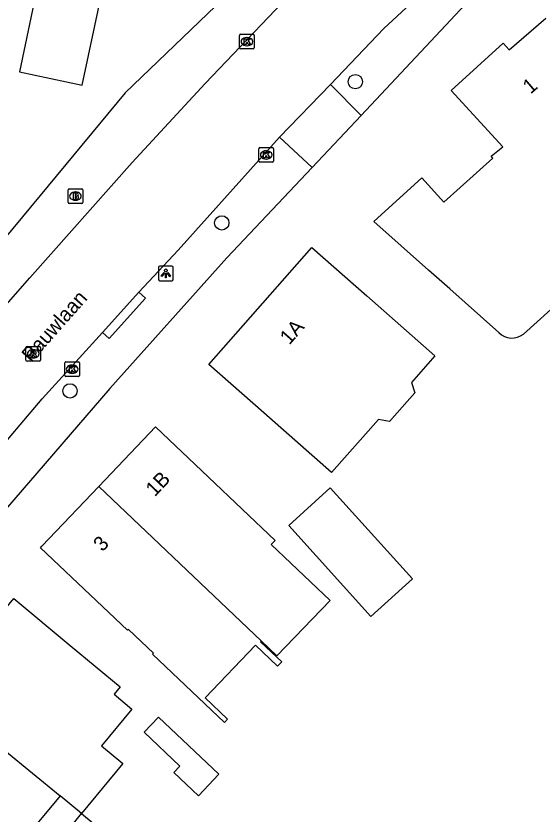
# Model space of a CAD drawing. Extents: x 161772 to 163123, y 383092 to 383917.
# Drawn here: x 162519.5 to 162555.4, y 383557.9 to 383612.4 of the extents above; entities that cross this region are included whole.
import ezdxf

# ---------------------------------------------------------------- set-up
doc = ezdxf.new("R2010")
doc.units = 0
for name, color, linetype in [('IMGEO_Boom', 7, 'Continuous'), ('IMGEO_Brandkraan', 7, 'Continuous'), ('IMGEO_Kolk', 7, 'Continuous'), ('IMGEO_Lichtpunt', 7, 'Continuous'), ('IMGEO_Openbare_ruimte_label', 7, 'Continuous'), ('IMGEO_Pand', 7, 'Continuous'), ('IMGEO_Pand_nummerreeks', 7, 'Continuous'), ('IMGEO_Rijbaan_lokaal_open', 7, 'Continuous'), ('IMGEO_Rioolput', 7, 'Continuous'), ('IMGEO_Voetpad_open', 7, 'Continuous')]:
    doc.layers.add(name, color=color, linetype=linetype)

msp = doc.modelspace()

# ---------------------------------------------------------------- linework, layer by layer
at = {"layer": 'IMGEO_Boom'}
for centre in [(162542.653, 383607.887), (162533.543, 383598.255), (162523.191, 383586.794)]:
    msp.add_circle(centre, 0.489, dxfattribs=at)
at = {"layer": 'IMGEO_Brandkraan'}
for p, q in [((162523.058, 383599.658), (162523.058, 383600.51)), ((162523.133, 383600.584), (162523.985, 383600.584)), ((162523.546, 383600.364), (162523.571, 383600.364)), ((162524.059, 383600.51), (162524.059, 383599.658)), ((162523.569, 383599.804), (162523.544, 383599.804)), ((162523.985, 383599.584), (162523.133, 383599.584))]:
    msp.add_line(p, q, dxfattribs=at)
for points in [[(162523.058, 383599.658), (162523.058, 383600.51)], [(162523.133, 383600.584), (162523.985, 383600.584)], [(162523.406, 383600.284), (162523.406, 383599.884), (162523.619, 383599.884)], [(162523.637, 383600.284), (162523.406, 383600.284)], [(162524.059, 383600.51), (162524.059, 383599.658)], [(162523.585, 383600.203), (162523.531, 383600.203), (162523.531, 383600.127)], [(162523.531, 383600.127), (162523.584, 383600.127)], [(162523.593, 383600.051), (162523.531, 383600.051), (162523.531, 383599.97)], [(162523.531, 383599.97), (162523.593, 383599.97)], [(162523.985, 383599.584), (162523.133, 383599.584)]]:
    msp.add_lwpolyline(points, dxfattribs=at)
for centre, radius, start, end in [((162523.135, 383600.508), 0.0765, 91.552, 178.448), ((162523.135, 383600.508), 0.0765, 91.552, 178.448), ((162523.641, 383600.139), 0.145, 59.4692, 91.5367), ((162523.666, 383600.186), 0.0922, 285.5137, 58.1501), ((162523.983, 383600.508), 0.0765, 1.552, 88.448), ((162523.983, 383600.508), 0.0765, 1.552, 88.448), ((162523.586, 383600.165), 0.0379, 267.8285, 90.9355), ((162523.594, 383600.01), 0.0404, 269.8759, 90.5077), ((162523.625, 383600.135), 0.251, 268.6676, 293.5347), ((162523.671, 383599.994), 0.105, 301.3115, 78.989), ((162523.135, 383599.66), 0.0765, 181.552, 268.448), ((162523.135, 383599.66), 0.0765, 181.552, 268.448), ((162523.983, 383599.66), 0.0765, 271.552, 358.448), ((162523.983, 383599.66), 0.0765, 271.552, 358.448)]:
    msp.add_arc(centre, radius, start, end, dxfattribs=at)
for centre, major_axis, ratio, start_param, end_param in [((162523.545, 383600.084), (-0.387, 0.002), 0.722429, 4.712389, 7.853982), ((162523.57, 383600.084), (-0.39, 0.002), 0.717154, 1.570796, 4.712389)]:
    msp.add_ellipse(centre, major_axis=major_axis, ratio=ratio, start_param=start_param, end_param=end_param, dxfattribs=at)
at = {"layer": 'IMGEO_Kolk'}
for p, q in [((162534.757, 383610.196), (162534.757, 383611.048)), ((162534.832, 383611.122), (162535.684, 383611.122)), ((162535.245, 383610.902), (162535.27, 383610.902)), ((162535.758, 383611.048), (162535.758, 383610.196)), ((162535.684, 383610.122), (162534.832, 383610.122)), ((162535.268, 383610.342), (162535.243, 383610.342)), ((162536.073, 383602.464), (162536.073, 383603.316)), ((162536.148, 383603.39), (162537, 383603.39)), ((162536.561, 383603.17), (162536.586, 383603.17)), ((162537.074, 383603.316), (162537.074, 383602.464)), ((162536.584, 383602.61), (162536.559, 383602.61)), ((162537, 383602.39), (162536.148, 383602.39)), ((162522.835, 383587.848), (162522.835, 383588.7)), ((162522.91, 383588.774), (162523.762, 383588.774)), ((162523.323, 383588.554), (162523.348, 383588.554)), ((162523.836, 383588.7), (162523.836, 383587.848)), ((162523.762, 383587.774), (162522.91, 383587.774)), ((162523.346, 383587.994), (162523.321, 383587.994))]:
    msp.add_line(p, q, dxfattribs=at)
for points in [[(162534.757, 383610.196), (162534.757, 383611.048)], [(162534.832, 383611.122), (162535.684, 383611.122)], [(162535.078, 383610.822), (162535.201, 383610.822), (162535.201, 383610.671), (162535.331, 383610.822), (162535.495, 383610.822), (162535.349, 383610.671), (162535.502, 383610.422), (162535.35, 383610.422), (162535.265, 383610.586), (162535.201, 383610.519), (162535.201, 383610.422), (162535.078, 383610.422), (162535.078, 383610.822)], [(162535.758, 383611.048), (162535.758, 383610.196)], [(162535.684, 383610.122), (162534.832, 383610.122)], [(162536.073, 383602.464), (162536.073, 383603.316)], [(162536.148, 383603.39), (162537, 383603.39)], [(162536.394, 383603.09), (162536.517, 383603.09), (162536.517, 383602.939), (162536.647, 383603.09), (162536.811, 383603.09), (162536.665, 383602.939), (162536.818, 383602.69), (162536.666, 383602.69), (162536.581, 383602.854), (162536.517, 383602.787), (162536.517, 383602.69), (162536.394, 383602.69), (162536.394, 383603.09)], [(162537.074, 383603.316), (162537.074, 383602.464)], [(162537, 383602.39), (162536.148, 383602.39)], [(162522.835, 383587.848), (162522.835, 383588.7)], [(162522.91, 383588.774), (162523.762, 383588.774)], [(162523.156, 383588.474), (162523.279, 383588.474), (162523.279, 383588.323), (162523.409, 383588.474), (162523.573, 383588.474), (162523.427, 383588.323), (162523.58, 383588.074), (162523.428, 383588.074), (162523.343, 383588.238), (162523.279, 383588.171), (162523.279, 383588.074), (162523.156, 383588.074), (162523.156, 383588.474)], [(162523.836, 383588.7), (162523.836, 383587.848)], [(162523.762, 383587.774), (162522.91, 383587.774)]]:
    msp.add_lwpolyline(points, dxfattribs=at)
for centre, start, end in [((162534.834, 383611.046), 91.552, 178.448), ((162534.834, 383611.046), 91.552, 178.448), ((162535.682, 383611.046), 1.552, 88.448), ((162535.682, 383611.046), 1.552, 88.448), ((162534.834, 383610.198), 181.552, 268.448), ((162534.834, 383610.198), 181.552, 268.448), ((162535.682, 383610.198), 271.552, 358.448), ((162535.682, 383610.198), 271.552, 358.448), ((162536.15, 383603.314), 91.552, 178.448), ((162536.15, 383603.314), 91.552, 178.448), ((162536.998, 383603.314), 1.552, 88.448), ((162536.998, 383603.314), 1.552, 88.448), ((162536.15, 383602.466), 181.552, 268.448), ((162536.15, 383602.466), 181.552, 268.448), ((162536.998, 383602.466), 271.552, 358.448), ((162536.998, 383602.466), 271.552, 358.448), ((162522.912, 383588.698), 91.552, 178.448), ((162522.912, 383588.698), 91.552, 178.448), ((162523.76, 383588.698), 1.552, 88.448), ((162523.76, 383588.698), 1.552, 88.448), ((162522.912, 383587.85), 181.552, 268.448), ((162522.912, 383587.85), 181.552, 268.448), ((162523.76, 383587.85), 271.552, 358.448), ((162523.76, 383587.85), 271.552, 358.448)]:
    msp.add_arc(centre, 0.0765, start, end, dxfattribs=at)
for centre, major_axis, ratio, start_param, end_param in [((162535.244, 383610.622), (-0.387, 0.002), 0.722429, 4.712389, 7.853982), ((162535.269, 383610.622), (-0.39, 0.002), 0.717154, 1.570796, 4.712389), ((162536.56, 383602.89), (-0.387, 0.002), 0.722429, 4.712389, 7.853982), ((162536.585, 383602.89), (-0.39, 0.002), 0.717154, 1.570796, 4.712389), ((162523.322, 383588.274), (-0.387, 0.002), 0.722429, 4.712389, 7.853982), ((162523.347, 383588.274), (-0.39, 0.002), 0.717154, 1.570796, 4.712389)]:
    msp.add_ellipse(centre, major_axis=major_axis, ratio=ratio, start_param=start_param, end_param=end_param, dxfattribs=at)
at = {"layer": 'IMGEO_Lichtpunt'}
for p, q in [((162529.228, 383595.213), (162529.228, 383594.406)), ((162529.228, 383595.213), (162529.228, 383594.406)), ((162530.13, 383595.308), (162529.322, 383595.308)), ((162530.13, 383595.308), (162529.322, 383595.308)), ((162530.224, 383594.406), (162530.224, 383595.213)), ((162530.224, 383594.406), (162530.224, 383595.213)), ((162529.322, 383594.312), (162530.13, 383594.312)), ((162529.322, 383594.312), (162530.13, 383594.312))]:
    msp.add_line(p, q, dxfattribs=at)
for points in [[(162529.602, 383594.877), (162529.641, 383594.849), (162529.453, 383594.587), (162529.415, 383594.614), (162529.602, 383594.877)], [(162529.704, 383594.829), (162529.751, 383594.829), (162529.751, 383594.507), (162529.704, 383594.507), (162529.704, 383594.829)], [(162529.814, 383594.849), (162529.852, 383594.876), (162530.039, 383594.614), (162530, 383594.586), (162529.814, 383594.849)]]:
    msp.add_lwpolyline(points, dxfattribs=at)
msp.add_circle((162529.727, 383595.011), 0.0994, dxfattribs=at)
for centre, start, end in [((162529.322, 383595.213), 90, 180), ((162529.322, 383595.213), 90, 180), ((162530.13, 383595.213), 0, 90), ((162530.13, 383595.213), 0, 90), ((162529.322, 383594.406), 180, 270), ((162529.322, 383594.406), 180, 270), ((162530.13, 383594.406), 270, 0), ((162530.13, 383594.406), 270, 360)]:
    msp.add_arc(centre, 0.0946, start, end, dxfattribs=at)
at = {"layer": 'IMGEO_Pand'}
for points in [[(162524.024, 383607.661), (162525.306, 383613.757), (162521.016, 383614.659), (162519.734, 383608.563), (162524.024, 383607.661)], [(162547.649, 383595.027), (162543.905, 383598.341), (162547.182, 383601.332), (162548.68, 383599.661), (162552.035, 383602.667), (162551.908, 383602.809), (162552.707, 383603.436), (162549.187, 383607.285), (162552.727, 383610.507), (162553.15, 383610.055), (162555.647, 383612.233)], [(162557.334, 383612.128), (162559.543, 383609.647), (162560.069, 383610.133), (162563.294, 383606.565), (162559.429, 383603.09), (162560.104, 383602.345), (162556.393, 383598.995), (162556.133, 383598.76), (162559.255, 383595.301), (162554.127, 383590.672)], [(162544.222, 383584.846), (162541.032, 383581.223), (162536.404, 383585.298), (162532.651, 383588.602), (162539.681, 383596.585), (162543.434, 383593.281), (162548.075, 383589.194), (162546.474, 383587.375), (162546.712, 383586.669), (162544.973, 383584.695), (162544.222, 383584.846)], [(162552.44, 383590.777), (162549.093, 383593.749), (162547.649, 383595.027)], [(162525.149, 383580.269), (162529.02, 383584.344), (162532.645, 383580.901), (162534.926, 383578.733), (162537.177, 383576.596), (162536.914, 383576.319), (162540.936, 383572.495), (162537.296, 383568.725), (162536.236, 383569.732)], [(162536.236, 383569.732), (162536.189, 383569.682), (162537.629, 383568.313), (162537.354, 383568.023), (162535.847, 383569.455), (162532.415, 383565.845), (162533.932, 383564.403), (162533.718, 383564.179), (162528.818, 383568.836), (162528.88, 383568.901), (162527.172, 383570.524), (162527.11, 383570.459), (162521.181, 383576.094), (162521.277, 383576.194), (162525.149, 383580.269)], [(162536.236, 383569.732), (162525.149, 383580.269)], [(162538.105, 383577.609), (162540.945, 383580.179), (162546.552, 383573.981), (162543.712, 383571.411), (162538.105, 383577.609)], [(162513.053, 383566.891), (162513.652, 383567.614), (162513.423, 383568.23), (162514.493, 383569.521), (162515.331, 383569.6), (162517.71, 383572.472), (162518.611, 383571.727), (162519.349, 383572.618), (162523.2, 383569.429), (162526.612, 383566.602), (162526.193, 383566.096), (162527.417, 383565.082), (162525.341, 383562.575), (162526.799, 383561.367), (162523.978, 383557.962)], [(162513.053, 383566.891), (162522.513, 383559.16)], [(162530.268, 383560.751), (162530.684, 383561.191), (162528.246, 383563.502), (162529.232, 383564.543), (162533.346, 383560.643), (162531.943, 383559.163), (162530.268, 383560.751)], [(162522.513, 383559.16), (162520.617, 383556.87), (162522.095, 383555.647), (162519.266, 383552.231)], [(162523.978, 383557.962), (162522.513, 383559.16)], [(162523.978, 383557.962), (162528.354, 383554.327), (162528.437, 383554.27), (162526.88, 383552.39), (162524.68, 383554.212), (162525.322, 383554.987), (162523.084, 383556.841), (162523.978, 383557.962)]]:
    msp.add_lwpolyline(points, dxfattribs=at)
msp.add_arc((162553.342, 383591.662), 1.264, 224.47, 308.4069, dxfattribs=at)
at = {"layer": 'IMGEO_Rijbaan_lokaal_open'}
for points in [[(162553.031, 383619.44), (162551.719, 383618.217), (162550.071, 383616.607), (162544.606, 383611.519), (162540.951, 383607.707)], [(162513.52, 383586.607), (162520.458, 383594.506), (162527.435, 383602.384), (162532.418, 383607.776), (162537.203, 383612.786), (162540.103, 383615.776)], [(162537.488, 383604.096), (162540.951, 383607.707)], [(162527.89, 383593.519), (162530.565, 383596.403), (162537.488, 383604.096)], [(162525.402, 383590.777), (162527.89, 383593.519)], [(162492.315, 383551.109), (162499.866, 383560.331), (162506.576, 383568.47), (162512.205, 383575.261), (162517.639, 383581.965), (162521.297, 383586.253), (162525.402, 383590.777)]]:
    msp.add_lwpolyline(points, dxfattribs=at)
at = {"layer": 'IMGEO_Rioolput'}
for p, q in [((162520.184, 383588.895), (162520.184, 383589.747)), ((162520.259, 383589.821), (162521.111, 383589.821)), ((162520.672, 383589.601), (162520.697, 383589.601)), ((162521.185, 383589.747), (162521.185, 383588.895)), ((162521.111, 383588.821), (162520.259, 383588.821)), ((162520.695, 383589.041), (162520.67, 383589.041))]:
    msp.add_line(p, q, dxfattribs=at)
for points in [[(162520.184, 383588.895), (162520.184, 383589.747)], [(162520.259, 383589.821), (162521.111, 383589.821)], [(162520.773, 383589.519), (162520.521, 383589.521), (162520.521, 383589.121)], [(162520.699, 383589.44), (162520.645, 383589.44), (162520.645, 383589.359)], [(162521.185, 383589.747), (162521.185, 383588.895)], [(162521.111, 383588.821), (162520.259, 383588.821)], [(162520.521, 383589.121), (162520.645, 383589.121), (162520.645, 383589.283), (162520.656, 383589.283)], [(162520.645, 383589.359), (162520.697, 383589.359)], [(162520.703, 383589.254), (162520.774, 383589.121), (162520.914, 383589.121), (162520.849, 383589.247)]]:
    msp.add_lwpolyline(points, dxfattribs=at)
for centre, radius, start, end in [((162520.261, 383589.745), 0.0765, 91.552, 178.448), ((162520.261, 383589.745), 0.0765, 91.552, 178.448), ((162520.681, 383589.548), 0.19, 274.7715, 282.9687), ((162520.705, 383589.344), 0.0964, 77.0061, 93.1865), ((162520.719, 383589.401), 0.0378, 276.6634, 79.6772), ((162520.772, 383589.409), 0.109, 350.3612, 89.416), ((162520.77, 383589.409), 0.112, 277.5842, 350.9817), ((162521.109, 383589.745), 0.0765, 1.552, 88.448), ((162521.109, 383589.745), 0.0765, 1.552, 88.448), ((162520.261, 383588.897), 0.0765, 181.552, 268.448), ((162520.261, 383588.897), 0.0765, 181.552, 268.448), ((162520.655, 383589.23), 0.0533, 26.0293, 88.6989), ((162520.754, 383589.194), 0.108, 29.5134, 73.7905), ((162521.109, 383588.897), 0.0765, 271.552, 358.448), ((162521.109, 383588.897), 0.0765, 271.552, 358.448)]:
    msp.add_arc(centre, radius, start, end, dxfattribs=at)
for centre, major_axis, ratio, start_param, end_param in [((162520.671, 383589.321), (-0.387, 0.002), 0.722429, 4.712389, 7.853982), ((162520.696, 383589.321), (-0.39, 0.002), 0.717154, 1.570796, 4.712389)]:
    msp.add_ellipse(centre, major_axis=major_axis, ratio=ratio, start_param=start_param, end_param=end_param, dxfattribs=at)
at = {"layer": 'IMGEO_Voetpad_open'}
for points in [[(162548.918, 383628.126), (162543.804, 383623.317), (162526.947, 383607.122), (162500, 383574.599), (162483.744, 383554.98), (162462.704, 383536.779), (162467.807, 383530.859), (162432.045, 383500), (162426.613, 383495.312)], [(162553.354, 383616.458), (162552.203, 383615.367), (162543.042, 383605.572)], [(162540.951, 383607.707), (162543.042, 383605.572)], [(162543.042, 383605.572), (162539.703, 383602.034)], [(162539.703, 383602.034), (162537.488, 383604.096)], [(162539.703, 383602.034), (162533.89, 383595.873), (162525.907, 383586.964), (162518.786, 383578.702), (162510.666, 383568.842), (162501.518, 383557.733), (162500, 383555.89), (162492.693, 383547.017), (162497.729, 383541.518), (162484.308, 383530.048)], [(162527.89, 383593.519), (162528.327, 383593.13), (162525.868, 383590.36), (162525.402, 383590.777)]]:
    msp.add_lwpolyline(points, dxfattribs=at)

# ---------------------------------------------------------------- texts
at = {"layer": 'IMGEO_Openbare_ruimte_label'}
msp.add_text('Pauwlaan', height=1, rotation=48.4045, dxfattribs=at).set_placement((162520.535, 383588.688))
at = {"layer": 'IMGEO_Pand_nummerreeks'}
for s, rotation, p in [('1', 40.7203, (162554.603, 383607.006)), ('1A', 48.6322, (162538.156, 383589.89)), ('1B', 46.467, (162528.971, 383579.53)), ('3', 46.4669, (162525.401, 383575.773))]:
    msp.add_text(s, height=1, rotation=rotation, dxfattribs=at).set_placement(p)

doc.saveas('drawing.dxf')
